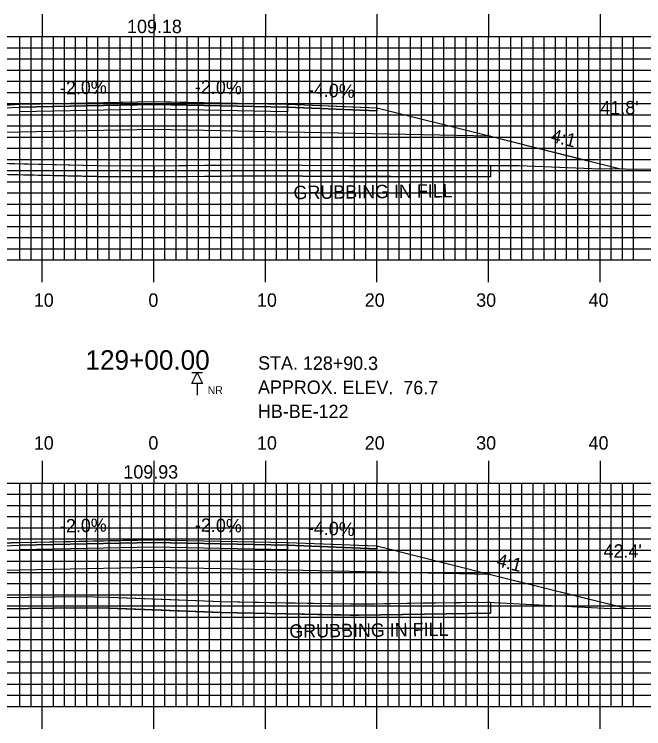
# Model space of a CAD drawing. Extents: x 1773596 to 1773940, y 442591 to 442811.
# Drawn here: x 1773749.6 to 1773806.1, y 442696.7 to 442760.7 of the extents above; entities that cross this region are included whole.
import ezdxf

# ---------------------------------------------------------------- set-up
doc = ezdxf.new("R2010")
doc.units = 0
for name, color, linetype in [('ANNOTATION', 7, 'Continuous'), ('BORING - NO REFUSAL', 7, 'Continuous'), ('D_Roadway_Centerline', 7, 'Continuous'), ('D_Roadway_Centerline_Text', 7, 'Continuous'), ('D_Roadway_Edge_Shoulder', 7, 'Continuous'), ('D_Roadway_Edge_TW', 7, 'Continuous'), ('D_Roadway_Pavement', 7, 'Continuous'), ('D_Roadway_SlopeLines', 7, 'Continuous'), ('D_Roadway_SubGrade', 7, 'Continuous'), ('D_Text_Standard', 7, 'Continuous'), ('GRUBBING IN FILL', 7, 'Continuous'), ('H_V ANNOTATION', 7, 'Continuous'), ('MAJOR', 7, 'Continuous'), ('MINOR', 7, 'Continuous'), ('S_Roadway_Centerline', 7, 'Continuous')]:
    doc.layers.add(name, color=color, linetype=linetype)

msp = doc.modelspace()

# ---------------------------------------------------------------- linework, layer by layer
at = {"layer": 'BORING - NO REFUSAL'}
for p, q in [((1773766.526, 442728.559), (1773765.566, 442728.559)), ((1773766.046, 442727.599), (1773766.046, 442726.54))]:
    msp.add_line(p, q, dxfattribs=at)
msp.add_lwpolyline([(1773766.046, 442728.559), (1773766.526, 442727.599), (1773765.566, 442727.599)], close=True, dxfattribs=at)
at = {"layer": 'D_Roadway_Centerline'}
for points in [[(1773712.795, 442747.466), (1773721.014, 442749.521), (1773730.146, 442751.804), (1773730.147, 442751.804), (1773749.27, 442752.569), (1773750.146, 442752.604), (1773753.801, 442752.677), (1773762.146, 442752.844), (1773765.553, 442752.776), (1773774.146, 442752.604), (1773777.853, 442752.456), (1773782.146, 442752.284), (1773792.32, 442749.74), (1773798.209, 442748.268), (1773803.986, 442746.824)], [(1773716.496, 442709.142), (1773721.014, 442710.271), (1773730.146, 442712.554), (1773730.147, 442712.555), (1773750.146, 442713.354), (1773759.4, 442713.539), (1773762.146, 442713.594), (1773774.146, 442713.354), (1773782.146, 442713.034), (1773792.32, 442710.49), (1773804.447, 442707.459), (1773804.593, 442707.422)]]:
    msp.add_lwpolyline(points, dxfattribs=at)
at = {"layer": 'D_Roadway_Edge_Shoulder'}
for points in [[(1773750.146, 442752.604), (1773730.146, 442751.804), (1773730.146, 442751.554), (1773750.146, 442752.354)], [(1773774.146, 442752.604), (1773782.146, 442752.284), (1773782.146, 442752.034), (1773774.146, 442752.354)], [(1773750.146, 442713.354), (1773730.146, 442712.554), (1773730.146, 442712.304), (1773750.146, 442713.104)], [(1773774.145, 442713.354), (1773782.146, 442713.034), (1773782.146, 442712.784), (1773774.145, 442713.104)]]:
    msp.add_lwpolyline(points, close=True, dxfattribs=at)
at = {"layer": 'D_Roadway_Edge_TW'}
for points in [[(1773750.146, 442752.354), (1773750.146, 442752.604), (1773762.146, 442752.844), (1773774.146, 442752.604), (1773774.146, 442752.354), (1773762.146, 442752.594)], [(1773750.146, 442713.104), (1773750.146, 442713.354), (1773762.146, 442713.594), (1773774.145, 442713.354), (1773774.145, 442713.104), (1773762.146, 442713.344)]]:
    msp.add_lwpolyline(points, close=True, dxfattribs=at)
at = {"layer": 'D_Roadway_Pavement'}
for points in [[(1773750.146, 442751.937), (1773750.146, 442752.354), (1773762.146, 442752.594), (1773774.146, 442752.354), (1773774.146, 442751.937), (1773762.146, 442752.177)], [(1773750.146, 442712.687), (1773750.146, 442713.104), (1773762.146, 442713.344), (1773774.145, 442713.104), (1773774.145, 442712.687), (1773762.146, 442712.927)]]:
    msp.add_lwpolyline(points, close=True, dxfattribs=at)
at = {"layer": 'D_Roadway_SlopeLines'}
for points in [[(1773782.146, 442752.284), (1773792.32, 442749.74), (1773803.986, 442746.824)], [(1773782.146, 442713.034), (1773792.32, 442710.49), (1773804.593, 442707.422)]]:
    msp.add_lwpolyline(points, dxfattribs=at)
at = {"layer": 'D_Roadway_SubGrade'}
for points in [[(1773750.146, 442750.104), (1773721.014, 442749.521), (1773730.146, 442751.804), (1773730.146, 442751.554), (1773750.146, 442752.354), (1773762.146, 442752.594), (1773774.146, 442752.354), (1773782.146, 442752.034), (1773782.146, 442752.284), (1773792.32, 442749.74), (1773774.146, 442750.104), (1773762.146, 442750.344)], [(1773750.146, 442710.854), (1773721.014, 442710.271), (1773730.146, 442712.554), (1773730.146, 442712.304), (1773750.146, 442713.104), (1773762.146, 442713.344), (1773774.145, 442713.104), (1773782.146, 442712.784), (1773782.146, 442713.034), (1773792.32, 442710.49), (1773774.145, 442710.854), (1773762.146, 442711.094)]]:
    msp.add_lwpolyline(points, close=True, dxfattribs=at)
at = {"layer": 'GRUBBING IN FILL'}
for p, q in [((1773792.32, 442747.12), (1773792.32, 442746.12)), ((1773792.32, 442747.12), (1773792.32, 442746.12)), ((1773792.32, 442707.994), (1773792.32, 442707.012)), ((1773792.32, 442707.994), (1773792.32, 442707.012))]:
    msp.add_line(p, q, dxfattribs=at)
for points in [[(1773731.972, 442747.569), (1773737.184, 442747.572), (1773747.155, 442747.348), (1773757.127, 442747.124), (1773762.146, 442747.102), (1773762.146, 442746.102), (1773757.113, 442746.124), (1773747.136, 442746.348), (1773737.159, 442746.573), (1773731.972, 442746.569)], [(1773762.146, 442747.102), (1773766.693, 442747.145), (1773771.311, 442747.189), (1773775.502, 442747.158), (1773779.693, 442747.126), (1773787.165, 442747.123), (1773792.32, 442747.12), (1773792.32, 442746.12), (1773789.742, 442746.121), (1773783.427, 442746.124), (1773775.501, 442746.158), (1773771.312, 442746.189), (1773766.695, 442746.145), (1773762.146, 442746.102)], [(1773762.146, 442747.102), (1773766.693, 442747.145), (1773771.311, 442747.189), (1773775.502, 442747.158), (1773779.693, 442747.126), (1773787.165, 442747.123), (1773792.32, 442747.12), (1773792.32, 442746.12), (1773789.742, 442746.121), (1773783.427, 442746.124), (1773775.501, 442746.158), (1773771.312, 442746.189), (1773766.695, 442746.145), (1773762.146, 442746.102)], [(1773731.972, 442708.646), (1773733.575, 442708.507), (1773735.151, 442708.496), (1773736.726, 442708.485), (1773741.423, 442708.436), (1773746.12, 442708.386), (1773750.848, 442708.442), (1773755.576, 442708.498), (1773758.141, 442708.46), (1773762.146, 442708.3), (1773762.146, 442707.299), (1773758.114, 442707.46), (1773755.575, 442707.498), (1773750.848, 442707.442), (1773746.12, 442707.386), (1773741.419, 442707.436), (1773736.718, 442707.485), (1773733.528, 442707.507), (1773731.972, 442707.643)], [(1773762.146, 442708.3), (1773768.213, 442708.058), (1773773.992, 442707.952), (1773779.772, 442707.845), (1773781.932, 442707.862), (1773786.279, 442707.925), (1773792.035, 442708.008), (1773792.32, 442707.994), (1773792.32, 442707.012), (1773786.424, 442706.927), (1773780.528, 442706.842), (1773773.972, 442706.952), (1773768.184, 442707.059), (1773762.146, 442707.299)], [(1773762.146, 442708.3), (1773768.213, 442708.058), (1773773.992, 442707.952), (1773779.772, 442707.845), (1773781.932, 442707.862), (1773786.279, 442707.925), (1773792.035, 442708.008), (1773792.32, 442707.994), (1773792.32, 442707.012), (1773786.424, 442706.927), (1773780.528, 442706.842), (1773773.972, 442706.952), (1773768.184, 442707.059), (1773762.146, 442707.299)]]:
    msp.add_lwpolyline(points, close=True, dxfattribs=at)
for points in [[(1773731.972, 442747.569), (1773737.184, 442747.572), (1773747.155, 442747.348), (1773757.127, 442747.124), (1773762.146, 442747.102), (1773762.146, 442746.102), (1773757.113, 442746.124), (1773747.136, 442746.348), (1773737.159, 442746.573), (1773731.972, 442746.569)], [(1773731.972, 442746.569), (1773735.577, 442746.589), (1773736.302, 442746.597), (1773737.159, 442746.573), (1773757.113, 442746.124), (1773762.077, 442746.102), (1773771.312, 442746.189), (1773779.689, 442746.126), (1773787.164, 442746.123), (1773792.32, 442746.12)], [(1773731.972, 442746.569), (1773735.577, 442746.589), (1773736.302, 442746.597), (1773737.159, 442746.573), (1773757.113, 442746.124), (1773762.077, 442746.102), (1773771.312, 442746.189), (1773779.689, 442746.126), (1773787.164, 442746.123), (1773792.32, 442746.12)], [(1773731.972, 442708.646), (1773733.575, 442708.507), (1773735.151, 442708.496), (1773736.726, 442708.485), (1773741.423, 442708.436), (1773746.12, 442708.386), (1773750.848, 442708.442), (1773755.576, 442708.498), (1773758.141, 442708.46), (1773762.146, 442708.3), (1773762.146, 442707.299), (1773758.114, 442707.46), (1773755.575, 442707.498), (1773750.848, 442707.442), (1773746.12, 442707.386), (1773741.419, 442707.436), (1773736.718, 442707.485), (1773733.528, 442707.507), (1773731.972, 442707.643)], [(1773731.972, 442707.643), (1773733.528, 442707.507), (1773736.718, 442707.485), (1773746.12, 442707.386), (1773755.575, 442707.498), (1773758.114, 442707.46), (1773768.184, 442707.059), (1773779.76, 442706.845), (1773780.528, 442706.842), (1773792.32, 442707.012)], [(1773731.972, 442707.643), (1773733.528, 442707.507), (1773736.718, 442707.485), (1773746.12, 442707.386), (1773755.575, 442707.498), (1773758.114, 442707.46), (1773768.184, 442707.059), (1773779.76, 442706.845), (1773780.528, 442706.842), (1773792.32, 442707.012)]]:
    msp.add_lwpolyline(points, dxfattribs=at)
at = {"layer": 'MAJOR'}
for p, q in [((1773752.146, 442760.669), (1773752.146, 442758.665)), ((1773762.146, 442760.669), (1773762.146, 442758.665)), ((1773772.146, 442760.669), (1773772.146, 442758.665)), ((1773782.146, 442760.669), (1773782.146, 442758.665)), ((1773792.146, 442760.669), (1773792.146, 442758.665)), ((1773802.146, 442760.669), (1773802.146, 442758.665)), ((1773622.146, 442758.665), (1773902.146, 442758.665)), ((1773622.146, 442758.665), (1773902.146, 442758.665)), ((1773752.146, 442738.665), (1773752.146, 442758.665)), ((1773762.146, 442738.665), (1773762.146, 442758.665)), ((1773772.146, 442738.665), (1773772.146, 442758.665)), ((1773782.146, 442738.665), (1773782.146, 442758.665)), ((1773792.146, 442738.665), (1773792.146, 442758.665)), ((1773802.146, 442738.665), (1773802.146, 442758.665)), ((1773622.146, 442753.665), (1773902.146, 442753.665)), ((1773622.146, 442748.665), (1773902.146, 442748.665)), ((1773622.146, 442743.665), (1773902.146, 442743.665)), ((1773622.146, 442738.665), (1773902.146, 442738.665)), ((1773622.146, 442738.665), (1773902.146, 442738.665)), ((1773752.146, 442736.661), (1773752.146, 442738.665)), ((1773762.146, 442736.661), (1773762.146, 442738.665)), ((1773772.146, 442736.661), (1773772.146, 442738.665)), ((1773782.146, 442736.661), (1773782.146, 442738.665)), ((1773792.146, 442736.661), (1773792.146, 442738.665)), ((1773802.146, 442736.661), (1773802.146, 442738.665)), ((1773752.146, 442720.669), (1773752.146, 442718.665)), ((1773762.146, 442720.669), (1773762.146, 442718.665)), ((1773772.146, 442720.669), (1773772.146, 442718.665)), ((1773782.146, 442720.669), (1773782.146, 442718.665)), ((1773792.146, 442720.669), (1773792.146, 442718.665)), ((1773802.146, 442720.669), (1773802.146, 442718.665)), ((1773622.146, 442718.665), (1773902.146, 442718.665)), ((1773622.146, 442718.665), (1773902.146, 442718.665)), ((1773752.146, 442698.665), (1773752.146, 442718.665)), ((1773762.146, 442698.665), (1773762.146, 442718.665)), ((1773772.146, 442698.665), (1773772.146, 442718.665)), ((1773782.146, 442698.665), (1773782.146, 442718.665)), ((1773792.146, 442698.665), (1773792.146, 442718.665)), ((1773802.146, 442698.665), (1773802.146, 442718.665)), ((1773622.146, 442713.665), (1773902.146, 442713.665)), ((1773622.146, 442708.665), (1773902.146, 442708.665)), ((1773622.146, 442703.665), (1773902.146, 442703.665)), ((1773622.146, 442698.665), (1773902.146, 442698.665)), ((1773622.146, 442698.665), (1773902.146, 442698.665)), ((1773752.146, 442696.661), (1773752.146, 442698.665)), ((1773762.146, 442696.661), (1773762.146, 442698.665)), ((1773772.146, 442696.661), (1773772.146, 442698.665)), ((1773782.146, 442696.661), (1773782.146, 442698.665)), ((1773792.146, 442696.661), (1773792.146, 442698.665)), ((1773802.146, 442696.661), (1773802.146, 442698.665))]:
    msp.add_line(p, q, dxfattribs=at)
at = {"layer": 'MINOR'}
for p, q in [((1773750.146, 442738.665), (1773750.146, 442758.665)), ((1773751.146, 442738.665), (1773751.146, 442758.665)), ((1773753.146, 442738.665), (1773753.146, 442758.665)), ((1773754.146, 442738.665), (1773754.146, 442758.665)), ((1773755.146, 442738.665), (1773755.146, 442758.665)), ((1773756.146, 442738.665), (1773756.146, 442758.665)), ((1773757.146, 442738.665), (1773757.146, 442758.665)), ((1773758.146, 442738.665), (1773758.146, 442758.665)), ((1773759.146, 442738.665), (1773759.146, 442758.665)), ((1773760.146, 442738.665), (1773760.146, 442758.665)), ((1773761.146, 442738.665), (1773761.146, 442758.665)), ((1773763.146, 442738.665), (1773763.146, 442758.665)), ((1773764.146, 442738.665), (1773764.146, 442758.665)), ((1773765.146, 442738.665), (1773765.146, 442758.665)), ((1773766.146, 442738.665), (1773766.146, 442758.665)), ((1773767.146, 442738.665), (1773767.146, 442758.665)), ((1773768.146, 442738.665), (1773768.146, 442758.665)), ((1773769.146, 442738.665), (1773769.146, 442758.665)), ((1773770.146, 442738.665), (1773770.146, 442758.665)), ((1773771.146, 442738.665), (1773771.146, 442758.665)), ((1773773.146, 442738.665), (1773773.146, 442758.665)), ((1773774.146, 442738.665), (1773774.146, 442758.665)), ((1773775.146, 442738.665), (1773775.146, 442758.665)), ((1773776.146, 442738.665), (1773776.146, 442758.665)), ((1773777.146, 442738.665), (1773777.146, 442758.665)), ((1773778.146, 442738.665), (1773778.146, 442758.665)), ((1773779.146, 442738.665), (1773779.146, 442758.665)), ((1773780.146, 442738.665), (1773780.146, 442758.665)), ((1773781.146, 442738.665), (1773781.146, 442758.665)), ((1773783.146, 442738.665), (1773783.146, 442758.665)), ((1773784.146, 442738.665), (1773784.146, 442758.665)), ((1773785.146, 442738.665), (1773785.146, 442758.665)), ((1773786.146, 442738.665), (1773786.146, 442758.665)), ((1773787.146, 442738.665), (1773787.146, 442758.665)), ((1773788.146, 442738.665), (1773788.146, 442758.665)), ((1773789.146, 442738.665), (1773789.146, 442758.665)), ((1773790.146, 442738.665), (1773790.146, 442758.665)), ((1773791.146, 442738.665), (1773791.146, 442758.665)), ((1773793.146, 442738.665), (1773793.146, 442758.665)), ((1773794.146, 442738.665), (1773794.146, 442758.665)), ((1773795.146, 442738.665), (1773795.146, 442758.665)), ((1773796.146, 442738.665), (1773796.146, 442758.665)), ((1773797.146, 442738.665), (1773797.146, 442758.665)), ((1773798.146, 442738.665), (1773798.146, 442758.665)), ((1773799.146, 442738.665), (1773799.146, 442758.665)), ((1773800.146, 442738.665), (1773800.146, 442758.665)), ((1773801.146, 442738.665), (1773801.146, 442758.665)), ((1773803.146, 442738.665), (1773803.146, 442758.665)), ((1773804.146, 442738.665), (1773804.146, 442758.665)), ((1773805.146, 442738.665), (1773805.146, 442758.665)), ((1773622.146, 442757.665), (1773902.146, 442757.665)), ((1773622.146, 442756.665), (1773902.146, 442756.665)), ((1773622.146, 442755.665), (1773902.146, 442755.665)), ((1773622.146, 442754.665), (1773902.146, 442754.665)), ((1773622.146, 442752.665), (1773902.146, 442752.665)), ((1773622.146, 442751.665), (1773902.146, 442751.665)), ((1773622.146, 442750.665), (1773902.146, 442750.665)), ((1773622.146, 442749.665), (1773902.146, 442749.665)), ((1773622.146, 442747.665), (1773902.146, 442747.665)), ((1773622.146, 442746.665), (1773902.146, 442746.665)), ((1773622.146, 442745.665), (1773902.146, 442745.665)), ((1773622.146, 442744.665), (1773902.146, 442744.665)), ((1773622.146, 442742.665), (1773902.146, 442742.665)), ((1773622.146, 442741.665), (1773902.146, 442741.665)), ((1773622.146, 442740.665), (1773902.146, 442740.665)), ((1773622.146, 442739.665), (1773902.146, 442739.665)), ((1773750.146, 442698.665), (1773750.146, 442718.665)), ((1773751.146, 442698.665), (1773751.146, 442718.665)), ((1773753.146, 442698.665), (1773753.146, 442718.665)), ((1773754.146, 442698.665), (1773754.146, 442718.665)), ((1773755.146, 442698.665), (1773755.146, 442718.665)), ((1773756.146, 442698.665), (1773756.146, 442718.665)), ((1773757.146, 442698.665), (1773757.146, 442718.665)), ((1773758.146, 442698.665), (1773758.146, 442718.665)), ((1773759.146, 442698.665), (1773759.146, 442718.665)), ((1773760.146, 442698.665), (1773760.146, 442718.665)), ((1773761.146, 442698.665), (1773761.146, 442718.665)), ((1773763.146, 442698.665), (1773763.146, 442718.665)), ((1773764.146, 442698.665), (1773764.146, 442718.665)), ((1773765.146, 442698.665), (1773765.146, 442718.665)), ((1773766.146, 442698.665), (1773766.146, 442718.665)), ((1773767.146, 442698.665), (1773767.146, 442718.665)), ((1773768.146, 442698.665), (1773768.146, 442718.665)), ((1773769.146, 442698.665), (1773769.146, 442718.665)), ((1773770.146, 442698.665), (1773770.146, 442718.665)), ((1773771.146, 442698.665), (1773771.146, 442718.665)), ((1773773.146, 442698.665), (1773773.146, 442718.665)), ((1773774.146, 442698.665), (1773774.146, 442718.665)), ((1773775.146, 442698.665), (1773775.146, 442718.665)), ((1773776.146, 442698.665), (1773776.146, 442718.665)), ((1773777.146, 442698.665), (1773777.146, 442718.665)), ((1773778.146, 442698.665), (1773778.146, 442718.665)), ((1773779.146, 442698.665), (1773779.146, 442718.665)), ((1773780.146, 442698.665), (1773780.146, 442718.665)), ((1773781.146, 442698.665), (1773781.146, 442718.665)), ((1773783.146, 442698.665), (1773783.146, 442718.665)), ((1773784.146, 442698.665), (1773784.146, 442718.665)), ((1773785.146, 442698.665), (1773785.146, 442718.665)), ((1773786.146, 442698.665), (1773786.146, 442718.665)), ((1773787.146, 442698.665), (1773787.146, 442718.665)), ((1773788.146, 442698.665), (1773788.146, 442718.665)), ((1773789.146, 442698.665), (1773789.146, 442718.665)), ((1773790.146, 442698.665), (1773790.146, 442718.665)), ((1773791.146, 442698.665), (1773791.146, 442718.665)), ((1773793.146, 442698.665), (1773793.146, 442718.665)), ((1773794.146, 442698.665), (1773794.146, 442718.665)), ((1773795.146, 442698.665), (1773795.146, 442718.665)), ((1773796.146, 442698.665), (1773796.146, 442718.665)), ((1773797.146, 442698.665), (1773797.146, 442718.665)), ((1773798.146, 442698.665), (1773798.146, 442718.665)), ((1773799.146, 442698.665), (1773799.146, 442718.665)), ((1773800.146, 442698.665), (1773800.146, 442718.665)), ((1773801.146, 442698.665), (1773801.146, 442718.665)), ((1773803.146, 442698.665), (1773803.146, 442718.665)), ((1773804.146, 442698.665), (1773804.146, 442718.665)), ((1773805.146, 442698.665), (1773805.146, 442718.665)), ((1773622.146, 442717.665), (1773902.146, 442717.665)), ((1773622.146, 442716.665), (1773902.146, 442716.665)), ((1773622.146, 442715.665), (1773902.146, 442715.665)), ((1773622.146, 442714.665), (1773902.146, 442714.665)), ((1773622.146, 442712.665), (1773902.146, 442712.665)), ((1773622.146, 442711.665), (1773902.146, 442711.665)), ((1773622.146, 442710.665), (1773902.146, 442710.665)), ((1773622.146, 442709.665), (1773902.146, 442709.665)), ((1773622.146, 442707.665), (1773902.146, 442707.665)), ((1773622.146, 442706.665), (1773902.146, 442706.665)), ((1773622.146, 442705.665), (1773902.146, 442705.665)), ((1773622.146, 442704.665), (1773902.146, 442704.665)), ((1773622.146, 442702.665), (1773902.146, 442702.665)), ((1773622.146, 442701.665), (1773902.146, 442701.665)), ((1773622.146, 442700.665), (1773902.146, 442700.665)), ((1773622.146, 442699.665), (1773902.146, 442699.665))]:
    msp.add_line(p, q, dxfattribs=at)
at = {"layer": 'S_Roadway_Centerline'}
for points in [[(1773690.451, 442747.637), (1773712.611, 442747.464), (1773712.928, 442747.467), (1773716.667, 442747.487), (1773735.569, 442747.589), (1773736.311, 442747.597), (1773737.184, 442747.572), (1773757.127, 442747.124), (1773762.075, 442747.102), (1773771.311, 442747.189), (1773779.693, 442747.126), (1773787.165, 442747.123), (1773794.899, 442747.118), (1773801.393, 442746.842), (1773810.383, 442746.778)], [(1773698.484, 442709.156), (1773704.924, 442709.084), (1773715.249, 442709.171), (1773729.858, 442708.83), (1773733.575, 442708.507), (1773736.726, 442708.485), (1773746.12, 442708.386), (1773755.576, 442708.498), (1773758.141, 442708.46), (1773768.213, 442708.058), (1773779.772, 442707.845), (1773780.523, 442707.842), (1773792.035, 442708.008), (1773802.508, 442707.473), (1773804.384, 442707.419), (1773814.803, 442707.544)]]:
    msp.add_lwpolyline(points, dxfattribs=at)

# ---------------------------------------------------------------- texts
at = {"layer": 'ANNOTATION'}
for s, rotation, p in [('-2.0%', 1.14571, (1773753.752, 442753.477)), ('-2.0%', 358.85423, (1773765.832, 442753.571)), ('-4.0%', 357.70929, (1773775.938, 442753.334)), ('4:1', 345.96576, (1773797.659, 442749.267)), ('-2.0%', 1.1458, (1773753.752, 442714.227)), ('-2.0%', 358.8542, (1773765.832, 442714.321)), ('-4.0%', 357.7095, (1773775.937, 442714.084)), ('4:1', 345.96304, (1773792.802, 442711.232))]:
    msp.add_text(s, height=1.2, rotation=rotation, dxfattribs=at).set_placement(p)
at = {"layer": 'BORING - NO REFUSAL'}
for s, p in [('STA. 128+90.3', (1773771.496, 442728.831)), ('APPROX. ELEV.  76.7', (1773771.489, 442726.671)), ('HB-BE-122', (1773771.482, 442724.511))]:
    msp.add_text(s, height=1.2, rotation=359.81416, dxfattribs=at).set_placement(p)
msp.add_text('NR', height=0.6998, dxfattribs=at).set_placement((1773766.979, 442726.644))
at = {"layer": 'D_Roadway_Centerline'}
for s, p in [('C', (1773762.141, 442752.844)), ('L', (1773762.146, 442752.837)), ('C', (1773762.141, 442713.594)), ('L', (1773762.146, 442713.587))]:
    msp.add_text(s, height=0.0146, dxfattribs=at).set_placement(p)
at = {"layer": 'D_Roadway_Centerline_Text'}
for s, p in [('109.18', (1773759.754, 442758.983)), ('109.93', (1773759.422, 442719.071))]:
    msp.add_text(s, height=1.2, dxfattribs=at).set_placement(p)
at = {"layer": 'D_Text_Standard'}
for s, p in [("41.8'", (1773802.174, 442751.701)), ("42.4'", (1773802.459, 442711.985))]:
    msp.add_text(s, height=1.2, dxfattribs=at).set_placement(p)
at = {"layer": 'GRUBBING IN FILL'}
for rotation, p in [(0.67625, (1773774.676, 442744.1)), (0.68105, (1773774.3, 442704.807))]:
    msp.add_text('GRUBBING IN FILL', height=1.2, rotation=rotation, dxfattribs=at).set_placement(p)
at = {"layer": 'H_V ANNOTATION'}
for s, height, p in [('10', 1.2, (1773751.397, 442734.465)), ('0', 1.2, (1773761.664, 442734.465)), ('10', 1.2, (1773771.397, 442734.465)), ('20', 1.2, (1773781.054, 442734.465)), ('30', 1.2, (1773791.043, 442734.465)), ('40', 1.2, (1773801.118, 442734.465)), ('129+00.00', 1.75, (1773756.029, 442728.821)), ('10', 1.2, (1773751.397, 442721.665)), ('0', 1.2, (1773761.664, 442721.665)), ('10', 1.2, (1773771.397, 442721.665)), ('20', 1.2, (1773781.054, 442721.665)), ('30', 1.2, (1773791.043, 442721.665)), ('40', 1.2, (1773801.118, 442721.665))]:
    msp.add_text(s, height=height, dxfattribs=at).set_placement(p)

doc.saveas('drawing.dxf')
